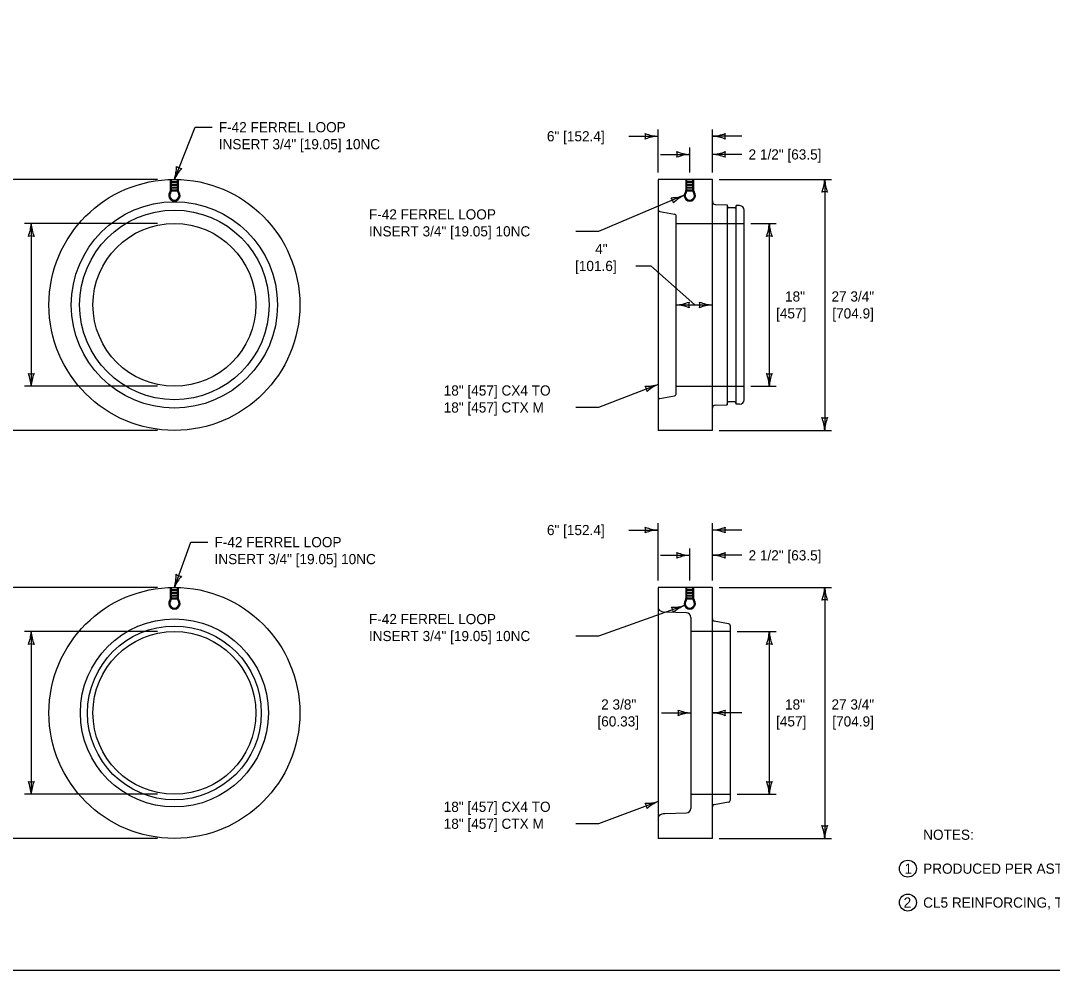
# Model space of a CAD drawing. Extents: x 49991.4 to 50021, y 49987.6 to 50011.4.
# Drawn here: x 50001.3 to 50007.38, y 49987.8 to 49993.4 of the extents above; entities that cross this region are included whole.
import ezdxf

# ---------------------------------------------------------------- set-up
doc = ezdxf.new("R2010")
doc.units = 0
for name, color, linetype in [('CONCRETE', 7, 'Continuous'), ('Level 1', 7, 'Continuous'), ('Level 2', 7, 'Continuous'), ('Level 3', 7, 'Continuous'), ('Level 4', 7, 'Continuous'), ('TEXT', 7, 'Continuous')]:
    doc.layers.add(name, color=color, linetype=linetype)

msp = doc.modelspace()

# ---------------------------------------------------------------- linework, layer by layer
at = {"layer": 'CONCRETE'}
msp.add_line((50005.3796, 49992.3361), (50005.3796, 49992.3311), dxfattribs=at)
at = {"layer": 'Level 1'}
for p, q in [((50005.0596, 49992.4628), (50005.0596, 49990.9828)), ((50005.3796, 49992.4628), (50005.0596, 49992.4628)), ((50005.3796, 49990.9828), (50005.3796, 49992.4628)), ((50005.3957, 49992.3144), (50005.466, 49992.3122)), ((50005.466, 49992.3122), (50005.466, 49991.1334)), ((50005.466, 49992.3122), (50005.4684, 49992.2988)), ((50005.5126, 49992.2946), (50005.4733, 49992.2946)), ((50005.5193, 49992.309), (50005.5175, 49992.2988)), ((50005.5193, 49991.1366), (50005.5193, 49992.309)), ((50005.5405, 49992.3083), (50005.5193, 49992.309)), ((50005.5663, 49991.1639), (50005.5663, 49992.2816)), ((50005.3957, 49991.1311), (50005.466, 49991.1334)), ((50005.466, 49991.1334), (50005.4684, 49991.1468)), ((50005.5126, 49991.1509), (50005.4733, 49991.1509)), ((50005.5193, 49991.1366), (50005.5175, 49991.1468)), ((50005.5405, 49991.1373), (50005.5193, 49991.1366)), ((50005.3796, 49991.1094), (50005.3796, 49991.1145)), ((50005.3796, 49990.9828), (50005.0596, 49990.9828)), ((50005.0596, 49990.0569), (50005.0596, 49988.5769)), ((50005.3796, 49990.0569), (50005.0596, 49990.0569)), ((50005.3796, 49988.5769), (50005.3796, 49990.0569)), ((50005.4754, 49989.8422), (50005.3905, 49989.8581)), ((50005.4863, 49988.8046), (50005.4863, 49989.8291)), ((50005.4754, 49988.7915), (50005.3905, 49988.7756)), ((50005.3796, 49988.5769), (50005.0596, 49988.5769))]:
    msp.add_line(p, q, dxfattribs=at)
msp.add_lwpolyline([(49999.3835, 49998.9992), (50016.7501, 49998.9992), (50016.7501, 49987.7988), (49999.3835, 49987.7988)], close=True, dxfattribs=at)
for centre, radius in [((50002.2065, 49991.7228), 0.74), ((50002.2065, 49991.7228), 0.6083), ((50002.2065, 49991.7228), 0.5589), ((50002.2065, 49991.7228), 0.48), ((50002.2065, 49989.3169), 0.74), ((50002.2065, 49989.3169), 0.5544), ((50002.2065, 49989.3169), 0.5123), ((50002.2065, 49989.3169), 0.48)]:
    msp.add_circle(centre, radius, dxfattribs=at)
for centre, radius, start, end in [((50005.3963, 49992.3311), 0.0167, 180, 268.167), ((50005.4733, 49992.2996), 0.005, 190, 270), ((50005.5126, 49992.2996), 0.005, 270, 350), ((50005.5396, 49992.2816), 0.0267, 0, 88.167), ((50005.3963, 49991.1145), 0.0167, 91.833, 180), ((50005.4733, 49991.1459), 0.005, 90, 170), ((50005.5126, 49991.1459), 0.005, 10, 90), ((50005.5396, 49991.1639), 0.0267, 271.833, 0), ((50005.3929, 49989.8713), 0.0133, 180, 259.38034), ((50005.4729, 49989.8291), 0.0133, 0, 79.38034), ((50005.3929, 49988.7625), 0.0133, 100.61966, 180), ((50005.4729, 49988.8046), 0.0133, 280.61966, 0)]:
    msp.add_arc(centre, radius, start, end, dxfattribs=at)
at = {"layer": 'Level 2'}
for centre in [(50006.5327, 49988.3986), (50006.5327, 49988.1986)]:
    msp.add_circle(centre, 0.05, dxfattribs=at)
at = {"layer": 'Level 3'}
for p, q in [((50004.8862, 49992.7172), (50005.0596, 49992.7172)), ((50005.0596, 49992.5028), (50005.0596, 49992.7572)), ((50005.3796, 49992.5028), (50005.3796, 49992.7572)), ((50005.553, 49992.7172), (50005.3796, 49992.7172)), ((50005.2463, 49992.5028), (50005.2463, 49992.65)), ((50005.3796, 49992.5028), (50005.3796, 49992.65)), ((50005.0728, 49992.61), (50005.2463, 49992.61)), ((50005.553, 49992.61), (50005.3796, 49992.61)), ((50002.1065, 49992.4628), (50000.9932, 49992.4628)), ((50005.4196, 49992.4628), (50006.0821, 49992.4628)), ((50006.0421, 49992.4628), (50006.0421, 49990.9828)), ((50002.1065, 49992.2028), (50001.322, 49992.2028)), ((50001.362, 49992.2028), (50001.362, 49991.2428)), ((50005.6063, 49992.2028), (50005.7551, 49992.2028)), ((50005.7151, 49992.2028), (50005.7151, 49991.2428)), ((50004.9276, 49991.9524), (50005.0173, 49991.9524)), ((50005.0173, 49991.9524), (50005.2763, 49991.7228)), ((50005.1663, 49991.7228), (50005.3796, 49991.7228)), ((50002.1065, 49991.2428), (50001.322, 49991.2428)), ((50005.6063, 49991.2428), (50005.7551, 49991.2428)), ((50002.1065, 49990.9828), (50000.9932, 49990.9828)), ((50005.4196, 49990.9828), (50006.0821, 49990.9828)), ((50004.8862, 49990.3953), (50005.0596, 49990.3953)), ((50005.0596, 49990.0969), (50005.0596, 49990.4353)), ((50005.3796, 49990.0969), (50005.3796, 49990.4353)), ((50005.553, 49990.3953), (50005.3796, 49990.3953)), ((50005.2463, 49990.0969), (50005.2463, 49990.2861)), ((50005.3796, 49990.0969), (50005.3796, 49990.2861)), ((50005.0728, 49990.2461), (50005.2463, 49990.2461)), ((50005.553, 49990.2461), (50005.3796, 49990.2461)), ((50002.1065, 49990.0569), (50000.9932, 49990.0569)), ((50005.4196, 49990.0569), (50006.0821, 49990.0569)), ((50006.0421, 49990.0569), (50006.0421, 49988.5769)), ((50002.1065, 49989.7969), (50001.322, 49989.7969)), ((50001.362, 49989.7969), (50001.362, 49988.8369)), ((50005.5263, 49989.7969), (50005.7551, 49989.7969)), ((50005.7151, 49989.7969), (50005.7151, 49988.8369)), ((50005.0795, 49989.3169), (50005.2529, 49989.3169)), ((50005.553, 49989.3169), (50005.3796, 49989.3169)), ((50002.1065, 49988.8369), (50001.322, 49988.8369)), ((50005.5263, 49988.8369), (50005.7551, 49988.8369)), ((50002.1065, 49988.5769), (50000.9932, 49988.5769)), ((50005.4196, 49988.5769), (50006.0821, 49988.5769))]:
    msp.add_line(p, q, dxfattribs=at)
for points in [[(50002.2065, 49992.4628), (50002.3284, 49992.7706), (50002.4284, 49992.7706)], [(50005.2129, 49992.3691), (50004.7084, 49992.1566), (50004.5741, 49992.1566)], [(50005.0596, 49991.2543), (50004.7084, 49991.1181), (50004.5741, 49991.1181)], [(50002.2065, 49990.0569), (50002.3032, 49990.324), (50002.4032, 49990.324)], [(50005.2154, 49989.9499), (50004.7084, 49989.7703), (50004.5741, 49989.7703)], [(50005.0596, 49988.7948), (50004.7084, 49988.6634), (50004.5741, 49988.6634)]]:
    msp.add_lwpolyline(points, dxfattribs=at)
for centre, radius, start, end in [((50005.0688, 49992.9393), 0.2223, 247.43895, 267.62245), ((50004.9314, 49992.7172), 0.0548, 342.12175, 17.84411), ((50005.071, 49992.4845), 0.233, 92.81025, 112.0601), ((50005.3682, 49992.9499), 0.233, 272.81025, 292.0601), ((50005.3704, 49992.4951), 0.2223, 67.43895, 87.62245), ((50005.5078, 49992.7172), 0.0548, 162.12175, 197.84411), ((50005.2555, 49992.8321), 0.2223, 247.43895, 267.62245), ((50005.118, 49992.61), 0.0548, 342.12175, 17.84411), ((50005.2577, 49992.3773), 0.233, 92.81025, 112.0601), ((50005.3682, 49992.8427), 0.233, 272.81025, 292.0601), ((50005.3704, 49992.3879), 0.2223, 67.43895, 87.62245), ((50005.5078, 49992.6099), 0.0548, 162.12175, 197.84411), ((50001.9859, 49992.5378), 0.233, 341.22891, 0.47876), ((50002.4097, 49992.3725), 0.2223, 135.85761, 156.04112), ((50002.2537, 49992.582), 0.0548, 230.54042, 266.26278), ((50005.8199, 49992.472), 0.2223, 337.43895, 357.62245), ((50006.2748, 49992.4742), 0.233, 182.81025, 202.0601), ((50005.1352, 49992.5773), 0.2223, 270.29356, 290.47707), ((50005.0948, 49992.3193), 0.0548, 4.97637, 40.69873), ((50005.3139, 49992.1591), 0.233, 115.66486, 134.91471), ((50006.042, 49992.3346), 0.0548, 72.12175, 107.84411), ((50001.1399, 49992.212), 0.2223, 337.43895, 357.62245), ((50001.5948, 49992.2142), 0.233, 182.81025, 202.0601), ((50005.493, 49992.212), 0.2223, 337.43895, 357.62245), ((50005.9478, 49992.2142), 0.233, 182.81025, 202.0601), ((50001.362, 49992.0746), 0.0548, 72.12175, 107.84411), ((50005.7151, 49992.0746), 0.0548, 72.12175, 107.84411), ((50005.1548, 49991.9555), 0.233, 272.81025, 292.0601), ((50005.2945, 49991.7227), 0.0548, 162.12175, 197.84411), ((50005.3888, 49991.9449), 0.2223, 247.43895, 267.62245), ((50005.2514, 49991.7228), 0.0548, 342.12175, 17.84411), ((50005.157, 49991.5006), 0.2223, 67.43895, 87.62245), ((50005.391, 49991.4901), 0.233, 92.81025, 112.0601), ((50001.3621, 49991.371), 0.0548, 252.12175, 287.84411), ((50001.1293, 49991.2314), 0.233, 2.81025, 22.0601), ((50001.5842, 49991.2336), 0.2223, 157.43895, 177.62245), ((50005.7151, 49991.371), 0.0548, 252.12175, 287.84411), ((50005.4824, 49991.2314), 0.233, 2.81025, 22.0601), ((50005.9372, 49991.2336), 0.2223, 157.43895, 177.62245), ((50004.9903, 49991.4655), 0.2223, 267.97455, 288.15806), ((50005.1519, 49991.0404), 0.233, 113.34585, 132.5957), ((50004.9395, 49991.2093), 0.0548, 2.65736, 38.37972), ((50006.0421, 49991.111), 0.0548, 252.12175, 287.84411), ((50005.8094, 49990.9714), 0.233, 2.81025, 22.0601), ((50006.2642, 49990.9736), 0.2223, 157.43895, 177.62245), ((50005.0688, 49990.6174), 0.2223, 247.43895, 267.62245), ((50004.9314, 49990.3953), 0.0548, 342.12175, 17.84411), ((50005.071, 49990.1626), 0.233, 92.81025, 112.0601), ((50005.3682, 49990.628), 0.233, 272.81025, 292.0601), ((50005.3704, 49990.1732), 0.2223, 67.43895, 87.62245), ((50005.5078, 49990.3952), 0.0548, 162.12175, 197.84411), ((50005.2555, 49990.4682), 0.2223, 247.43895, 267.62245), ((50005.118, 49990.2461), 0.0548, 342.12175, 17.84411), ((50005.2577, 49990.0134), 0.233, 92.81025, 112.0601), ((50005.3682, 49990.4788), 0.233, 272.81025, 292.0601), ((50005.3704, 49990.0239), 0.2223, 67.43895, 87.62245), ((50005.5078, 49990.246), 0.0548, 162.12175, 197.84411), ((50001.9838, 49990.1252), 0.233, 342.93813, 2.18798), ((50002.4123, 49989.9727), 0.2223, 137.56683, 157.75034), ((50002.2501, 49990.1774), 0.0548, 232.24964, 267.972), ((50005.8199, 49990.0661), 0.2223, 337.43895, 357.62245), ((50006.2748, 49990.0683), 0.233, 182.81025, 202.0601), ((50006.042, 49989.9286), 0.0548, 72.12175, 107.84411), ((50005.1498, 49990.1623), 0.2223, 266.96524, 287.14875), ((50005.0945, 49989.9071), 0.0548, 1.64805, 37.37041), ((50005.3039, 49989.7344), 0.233, 112.33654, 131.58639), ((50001.1399, 49989.8061), 0.2223, 337.43895, 357.62245), ((50001.5948, 49989.8083), 0.233, 182.81025, 202.0601), ((50005.493, 49989.8061), 0.2223, 337.43895, 357.62245), ((50005.9478, 49989.8083), 0.233, 182.81025, 202.0601), ((50001.362, 49989.6686), 0.0548, 72.12175, 107.84411), ((50005.7151, 49989.6686), 0.0548, 72.12175, 107.84411), ((50005.1247, 49989.3169), 0.0548, 342.12175, 17.84411), ((50005.2644, 49989.0841), 0.233, 92.81025, 112.0601), ((50005.2622, 49989.539), 0.2223, 247.43895, 267.62245), ((50005.3682, 49989.5496), 0.233, 272.81025, 292.0601), ((50005.3704, 49989.0947), 0.2223, 67.43895, 87.62245), ((50005.5078, 49989.3168), 0.0548, 162.12175, 197.84411), ((50001.3621, 49988.9651), 0.0548, 252.12175, 287.84411), ((50001.1293, 49988.8254), 0.233, 2.81025, 22.0601), ((50001.5842, 49988.8276), 0.2223, 157.43895, 177.62245), ((50005.7151, 49988.9651), 0.0548, 252.12175, 287.84411), ((50005.4824, 49988.8254), 0.233, 2.81025, 22.0601), ((50005.9372, 49988.8276), 0.2223, 157.43895, 177.62245), ((50004.9903, 49989.0061), 0.2223, 267.97455, 288.15806), ((50004.9395, 49988.7499), 0.0548, 2.65736, 38.37972), ((50005.1519, 49988.5809), 0.233, 113.34585, 132.5957), ((50006.0421, 49988.7051), 0.0548, 252.12175, 287.84411), ((50005.8094, 49988.5654), 0.233, 2.81025, 22.0601), ((50006.2642, 49988.5676), 0.2223, 157.43895, 177.62245)]:
    msp.add_arc(centre, radius, start, end, dxfattribs=at)
at = {"layer": 'Level 4'}
for p, q in [((50002.1843, 49992.4004), (50002.1843, 49992.4628)), ((50002.1843, 49992.4628), (50002.2287, 49992.4628)), ((50002.1899, 49992.4004), (50002.1899, 49992.4628)), ((50002.2232, 49992.4628), (50002.2232, 49992.4004)), ((50002.2287, 49992.4628), (50002.2287, 49992.4004)), ((50005.224, 49992.4004), (50005.224, 49992.4628)), ((50005.2296, 49992.4004), (50005.2296, 49992.4628)), ((50005.2629, 49992.4628), (50005.2629, 49992.4004)), ((50005.2685, 49992.4628), (50005.2685, 49992.4004)), ((50002.1899, 49992.4507), (50002.2232, 49992.4507)), ((50002.1899, 49992.446), (50002.2232, 49992.446)), ((50002.1899, 49992.4339), (50002.2232, 49992.4339)), ((50002.1899, 49992.4292), (50002.2232, 49992.4292)), ((50002.1899, 49992.4172), (50002.2232, 49992.4172)), ((50002.1899, 49992.4125), (50002.2232, 49992.4125)), ((50005.2296, 49992.4507), (50005.2629, 49992.4507)), ((50005.2296, 49992.446), (50005.2629, 49992.446)), ((50005.2296, 49992.4339), (50005.2629, 49992.4339)), ((50005.2296, 49992.4292), (50005.2629, 49992.4292)), ((50005.2296, 49992.4172), (50005.2629, 49992.4172)), ((50005.2296, 49992.4125), (50005.2629, 49992.4125)), ((50002.1826, 49992.3929), (50002.1831, 49992.3942)), ((50002.1878, 49992.3909), (50002.1883, 49992.3921)), ((50002.1894, 49992.3957), (50002.2237, 49992.3957)), ((50002.1899, 49992.4004), (50002.2232, 49992.4004)), ((50002.2253, 49992.3909), (50002.2248, 49992.3921)), ((50002.2304, 49992.3929), (50002.2299, 49992.3942)), ((50005.2223, 49992.3929), (50005.2228, 49992.3942)), ((50005.2275, 49992.3909), (50005.228, 49992.3921)), ((50005.2291, 49992.3957), (50005.2634, 49992.3957)), ((50005.2296, 49992.4004), (50005.2629, 49992.4004)), ((50005.265, 49992.3909), (50005.2645, 49992.3921)), ((50005.2702, 49992.3929), (50005.2697, 49992.3942)), ((50005.0705, 49992.2741), (50005.1554, 49992.2581)), ((50005.1663, 49991.2005), (50005.1663, 49992.245)), ((50005.1663, 49992.2028), (50005.5663, 49992.2028)), ((50005.0705, 49991.1715), (50005.1554, 49991.1874)), ((50005.1663, 49991.2428), (50005.5663, 49991.2428)), ((50002.1843, 49989.9945), (50002.1843, 49990.0569)), ((50002.1843, 49990.0569), (50002.2287, 49990.0569)), ((50002.1899, 49989.9945), (50002.1899, 49990.0569)), ((50002.1899, 49990.0448), (50002.2232, 49990.0448)), ((50002.1899, 49990.0401), (50002.2232, 49990.0401)), ((50002.1899, 49990.028), (50002.2232, 49990.028)), ((50002.2232, 49990.0569), (50002.2232, 49989.9945)), ((50002.2287, 49990.0569), (50002.2287, 49989.9945)), ((50005.224, 49989.9945), (50005.224, 49990.0569)), ((50005.2296, 49989.9945), (50005.2296, 49990.0569)), ((50005.2296, 49990.0448), (50005.2629, 49990.0448)), ((50005.2296, 49990.0401), (50005.2629, 49990.0401)), ((50005.2296, 49990.028), (50005.2629, 49990.028)), ((50005.2629, 49990.0569), (50005.2629, 49989.9945)), ((50005.2685, 49990.0569), (50005.2685, 49989.9945)), ((50002.1826, 49989.987), (50002.1831, 49989.9883)), ((50002.1878, 49989.9849), (50002.1883, 49989.9862)), ((50002.1894, 49989.9898), (50002.2237, 49989.9898)), ((50002.1899, 49990.0233), (50002.2232, 49990.0233)), ((50002.1899, 49990.0113), (50002.2232, 49990.0113)), ((50002.1899, 49990.0066), (50002.2232, 49990.0066)), ((50002.1899, 49989.9945), (50002.2232, 49989.9945)), ((50002.2253, 49989.9849), (50002.2248, 49989.9862)), ((50002.2304, 49989.987), (50002.2299, 49989.9883)), ((50005.2223, 49989.987), (50005.2228, 49989.9883)), ((50005.2275, 49989.9849), (50005.228, 49989.9862)), ((50005.2291, 49989.9898), (50005.2634, 49989.9898)), ((50005.2296, 49990.0233), (50005.2629, 49990.0233)), ((50005.2296, 49990.0113), (50005.2629, 49990.0113)), ((50005.2296, 49990.0066), (50005.2629, 49990.0066)), ((50005.2296, 49989.9945), (50005.2629, 49989.9945)), ((50005.265, 49989.9849), (50005.2645, 49989.9862)), ((50005.2702, 49989.987), (50005.2697, 49989.9883)), ((50005.2271, 49989.907), (50005.0996, 49989.911)), ((50005.2529, 49989.8803), (50005.2529, 49988.7534)), ((50005.4863, 49989.7969), (50005.2529, 49989.7969)), ((50005.2529, 49988.8369), (50005.4863, 49988.8369)), ((50005.2271, 49988.7267), (50005.0996, 49988.7227))]:
    msp.add_line(p, q, dxfattribs=at)
for centre, radius, start, end in [((50002.2065, 49992.3683), 0.0333, 141.99267, 38.00733), ((50002.2065, 49992.3683), 0.0278, 141.99267, 38.00733), ((50002.1671, 49992.3991), 0.0167, 321.99267, 338.19859), ((50002.1676, 49992.4004), 0.0167, 338.19859, 0), ((50002.1671, 49992.3991), 0.0222, 321.99267, 338.19859), ((50002.1676, 49992.4004), 0.0222, 338.19859, 0), ((50002.2454, 49992.4004), 0.0222, 180, 201.80141), ((50002.2459, 49992.3991), 0.0222, 201.80141, 218.00733), ((50002.2454, 49992.4004), 0.0167, 180, 201.80141), ((50002.2459, 49992.3991), 0.0167, 201.80141, 218.00733), ((50005.2463, 49992.3683), 0.0333, 141.99267, 38.00733), ((50005.2463, 49992.3683), 0.0278, 141.99267, 38.00733), ((50005.2069, 49992.3991), 0.0167, 321.99267, 338.19859), ((50005.2074, 49992.4004), 0.0167, 338.19859, 0), ((50005.2069, 49992.3991), 0.0222, 321.99267, 338.19859), ((50005.2074, 49992.4004), 0.0222, 338.19859, 0), ((50005.2852, 49992.4004), 0.0222, 180, 201.80141), ((50005.2857, 49992.3991), 0.0222, 201.80141, 218.00733), ((50005.2852, 49992.4004), 0.0167, 180, 201.80141), ((50005.2857, 49992.3991), 0.0167, 201.80141, 218.00733), ((50005.0729, 49992.2872), 0.0133, 180, 259.38034), ((50005.1529, 49992.245), 0.0133, 0, 79.38034), ((50005.1529, 49991.2005), 0.0133, 280.61966, 0), ((50005.0729, 49991.1584), 0.0133, 100.61966, 180), ((50002.2065, 49989.9624), 0.0333, 141.99267, 38.00733), ((50002.2065, 49989.9624), 0.0278, 141.99267, 38.00733), ((50002.1671, 49989.9932), 0.0167, 321.99267, 338.19859), ((50002.1676, 49989.9945), 0.0167, 338.19859, 0), ((50002.1671, 49989.9932), 0.0222, 321.99267, 338.19859), ((50002.1676, 49989.9945), 0.0222, 338.19859, 0), ((50002.2454, 49989.9945), 0.0222, 180, 201.80141), ((50002.2459, 49989.9932), 0.0222, 201.80141, 218.00733), ((50002.2454, 49989.9945), 0.0167, 180, 201.80141), ((50002.2459, 49989.9932), 0.0167, 201.80141, 218.00733), ((50005.2463, 49989.9624), 0.0333, 141.99267, 38.00733), ((50005.2463, 49989.9624), 0.0278, 141.99267, 38.00733), ((50005.2069, 49989.9932), 0.0167, 321.99267, 338.19859), ((50005.2074, 49989.9945), 0.0167, 338.19859, 0), ((50005.2069, 49989.9932), 0.0222, 321.99267, 338.19859), ((50005.2074, 49989.9945), 0.0222, 338.19859, 0), ((50005.2852, 49989.9945), 0.0222, 180, 201.80141), ((50005.2857, 49989.9932), 0.0222, 201.80141, 218.00733), ((50005.2852, 49989.9945), 0.0167, 180, 201.80141), ((50005.2857, 49989.9932), 0.0167, 201.80141, 218.00733), ((50005.0729, 49989.9341), 0.0133, 180, 232.2256), ((50005.1015, 49989.971), 0.06, 232.2256, 268.167), ((50005.2263, 49989.8803), 0.0267, 0, 88.167), ((50005.2263, 49988.7534), 0.0267, 271.833, 0), ((50005.0729, 49988.6996), 0.0133, 127.7744, 180), ((50005.1015, 49988.6627), 0.06, 91.833, 127.7744)]:
    msp.add_arc(centre, radius, start, end, dxfattribs=at)
at = {"layer": 'TEXT'}
for p, q in [((50005.224, 49992.4628), (50005.2685, 49992.4628)), ((50005.224, 49990.0569), (50005.2685, 49990.0569))]:
    msp.add_line(p, q, dxfattribs=at)

# ---------------------------------------------------------------- texts
at = {"layer": 'Level 2'}
for s, p in [('F-42 FERREL LOOP ', (50002.4684, 49992.7406)), ('6" [152.4]', (50004.4037, 49992.6872)), ('INSERT 3/4" [19.05] 10NC', (50002.4684, 49992.6406)), ('2 1/2" [63.5]', (50005.593, 49992.58)), ('F-42 FERREL LOOP', (50003.3539, 49992.2266)), ('INSERT 3/4" [19.05] 10NC', (50003.3539, 49992.1266)), ('18"', (50005.808, 49991.7428)), ('27 3/4"', (50006.0821, 49991.7428)), ('[457]', (50005.7551, 49991.6428)), ('[704.9]', (50006.0871, 49991.6428)), ('18" [457] CX4 TO ', (50003.7949, 49991.1881)), ('18" [457] CTX M', (50003.7949, 49991.0881)), ('6" [152.4]', (50004.4037, 49990.3653)), ('F-42 FERREL LOOP ', (50002.4432, 49990.294)), ('2 1/2" [63.5]', (50005.593, 49990.2161)), ('INSERT 3/4" [19.05] 10NC', (50002.4432, 49990.194)), ('F-42 FERREL LOOP ', (50003.3539, 49989.8403)), ('INSERT 3/4" [19.05] 10NC', (50003.3539, 49989.7403)), ('18"', (50005.808, 49989.3369)), ('27 3/4"', (50006.0821, 49989.3369)), ('[457]', (50005.7551, 49989.2369)), ('[704.9]', (50006.0871, 49989.2369)), ('18" [457] CX4 TO ', (50003.7949, 49988.7334)), ('18" [457] CTX M', (50003.7949, 49988.6334)), ('NOTES:', (50006.6227, 49988.5686)), ('1', (50006.5129, 49988.3686)), ('PRODUCED PER ASTM C76', (50006.6227, 49988.3686)), ('2', (50006.5075, 49988.1686)), ('CL5 REINFORCING, TYPE 5 CEMENT', (50006.6227, 49988.1686))]:
    msp.add_text(s, height=0.06, dxfattribs=at).set_placement(p)
for s, p in [('4"', (50004.6883, 49992.0224)), ('[101.6]', (50004.5696, 49991.9224))]:
    msp.add_text(s, height=0.06, rotation=360, dxfattribs=at).set_placement(p)
at = {"layer": 'Level 3'}
for s, p in [('2 3/8"', (50004.7236, 49989.3369)), ('[60.33]', (50004.7017, 49989.2369))]:
    msp.add_text(s, height=0.06, rotation=360, dxfattribs=at).set_placement(p)

doc.saveas('drawing.dxf')
